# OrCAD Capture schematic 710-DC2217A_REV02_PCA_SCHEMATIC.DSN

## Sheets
1 PAGE1: size Custom; note: I²C / SMBUS TRANSLATOR
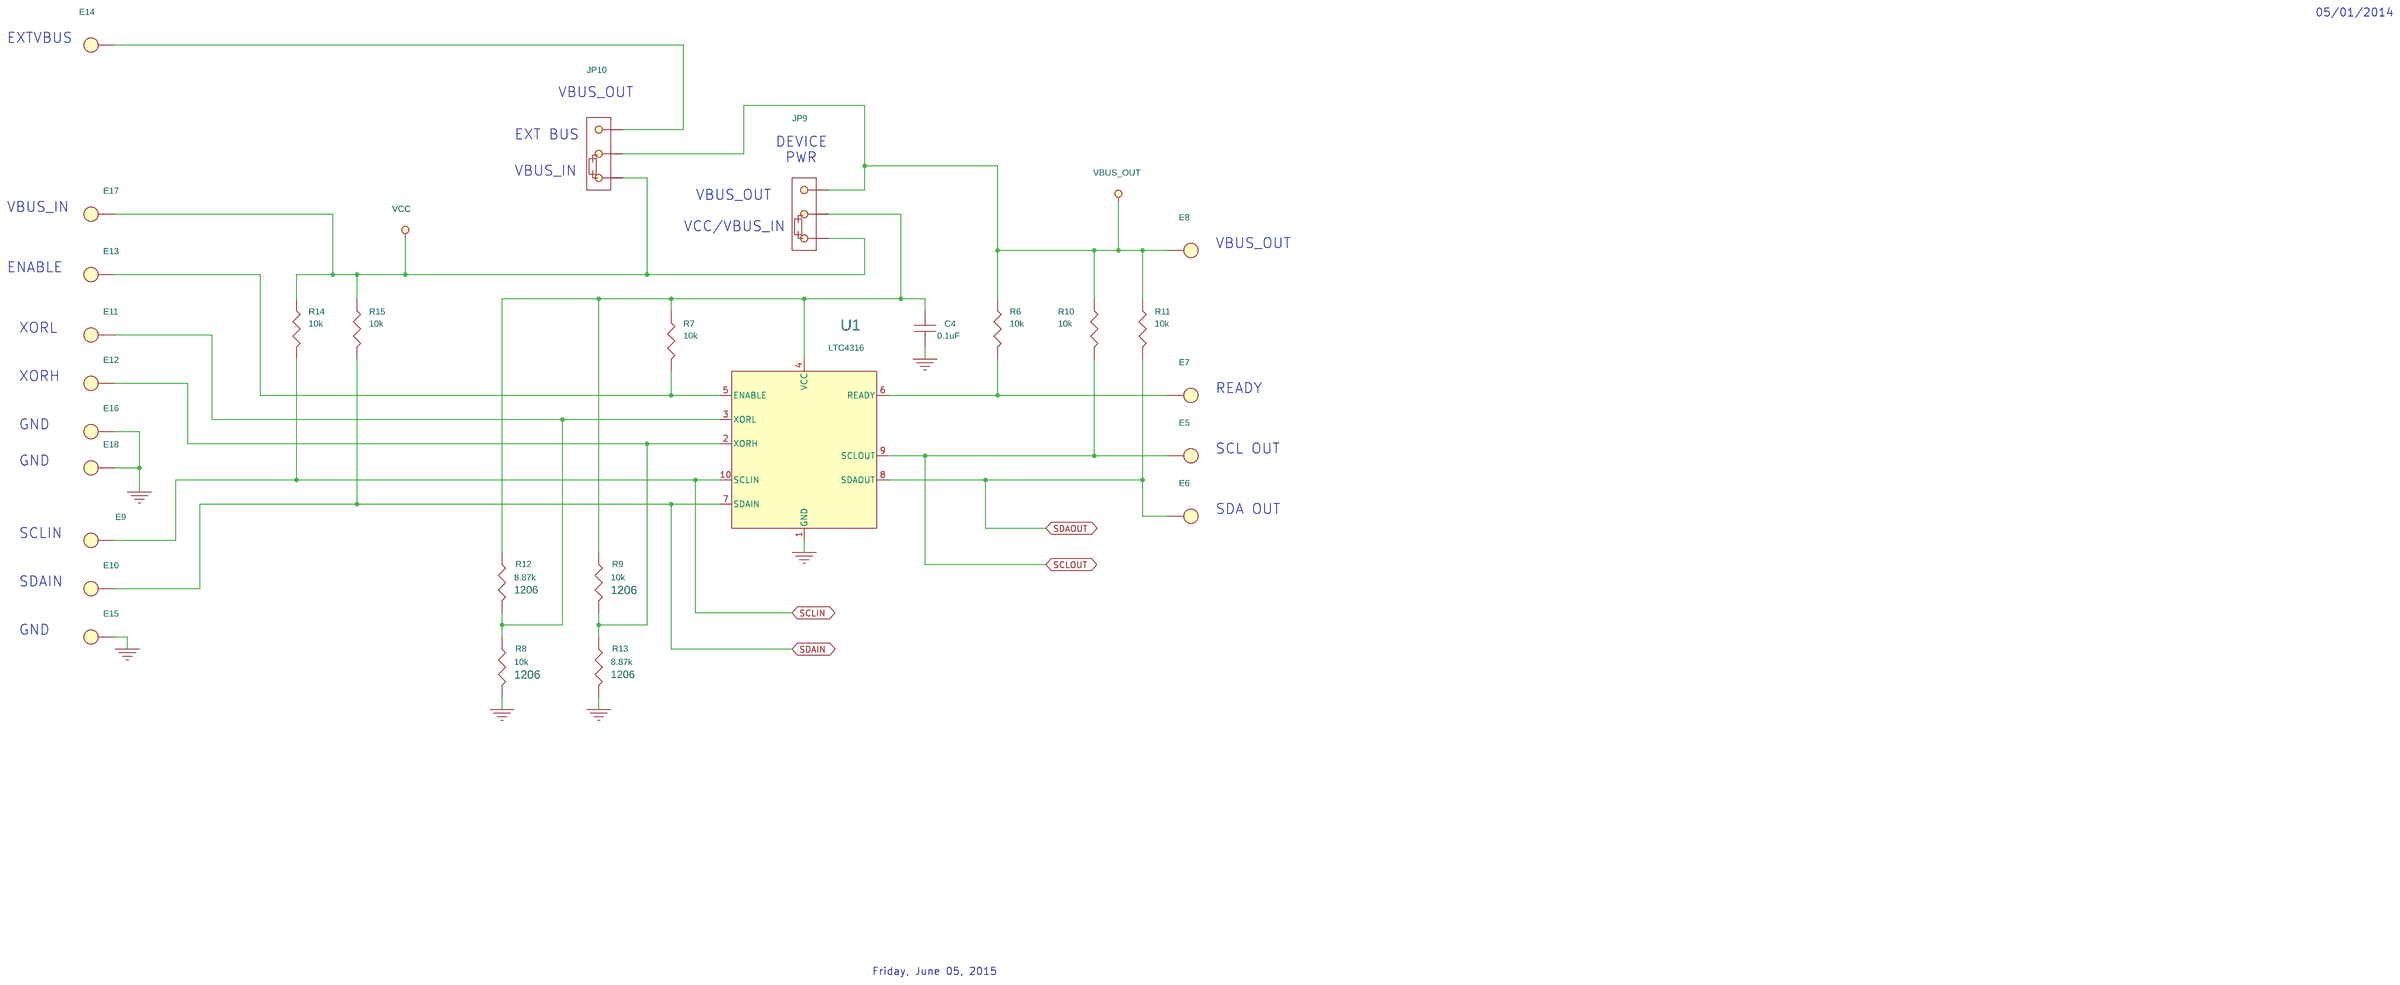
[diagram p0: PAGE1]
2 PAGE2: size Custom
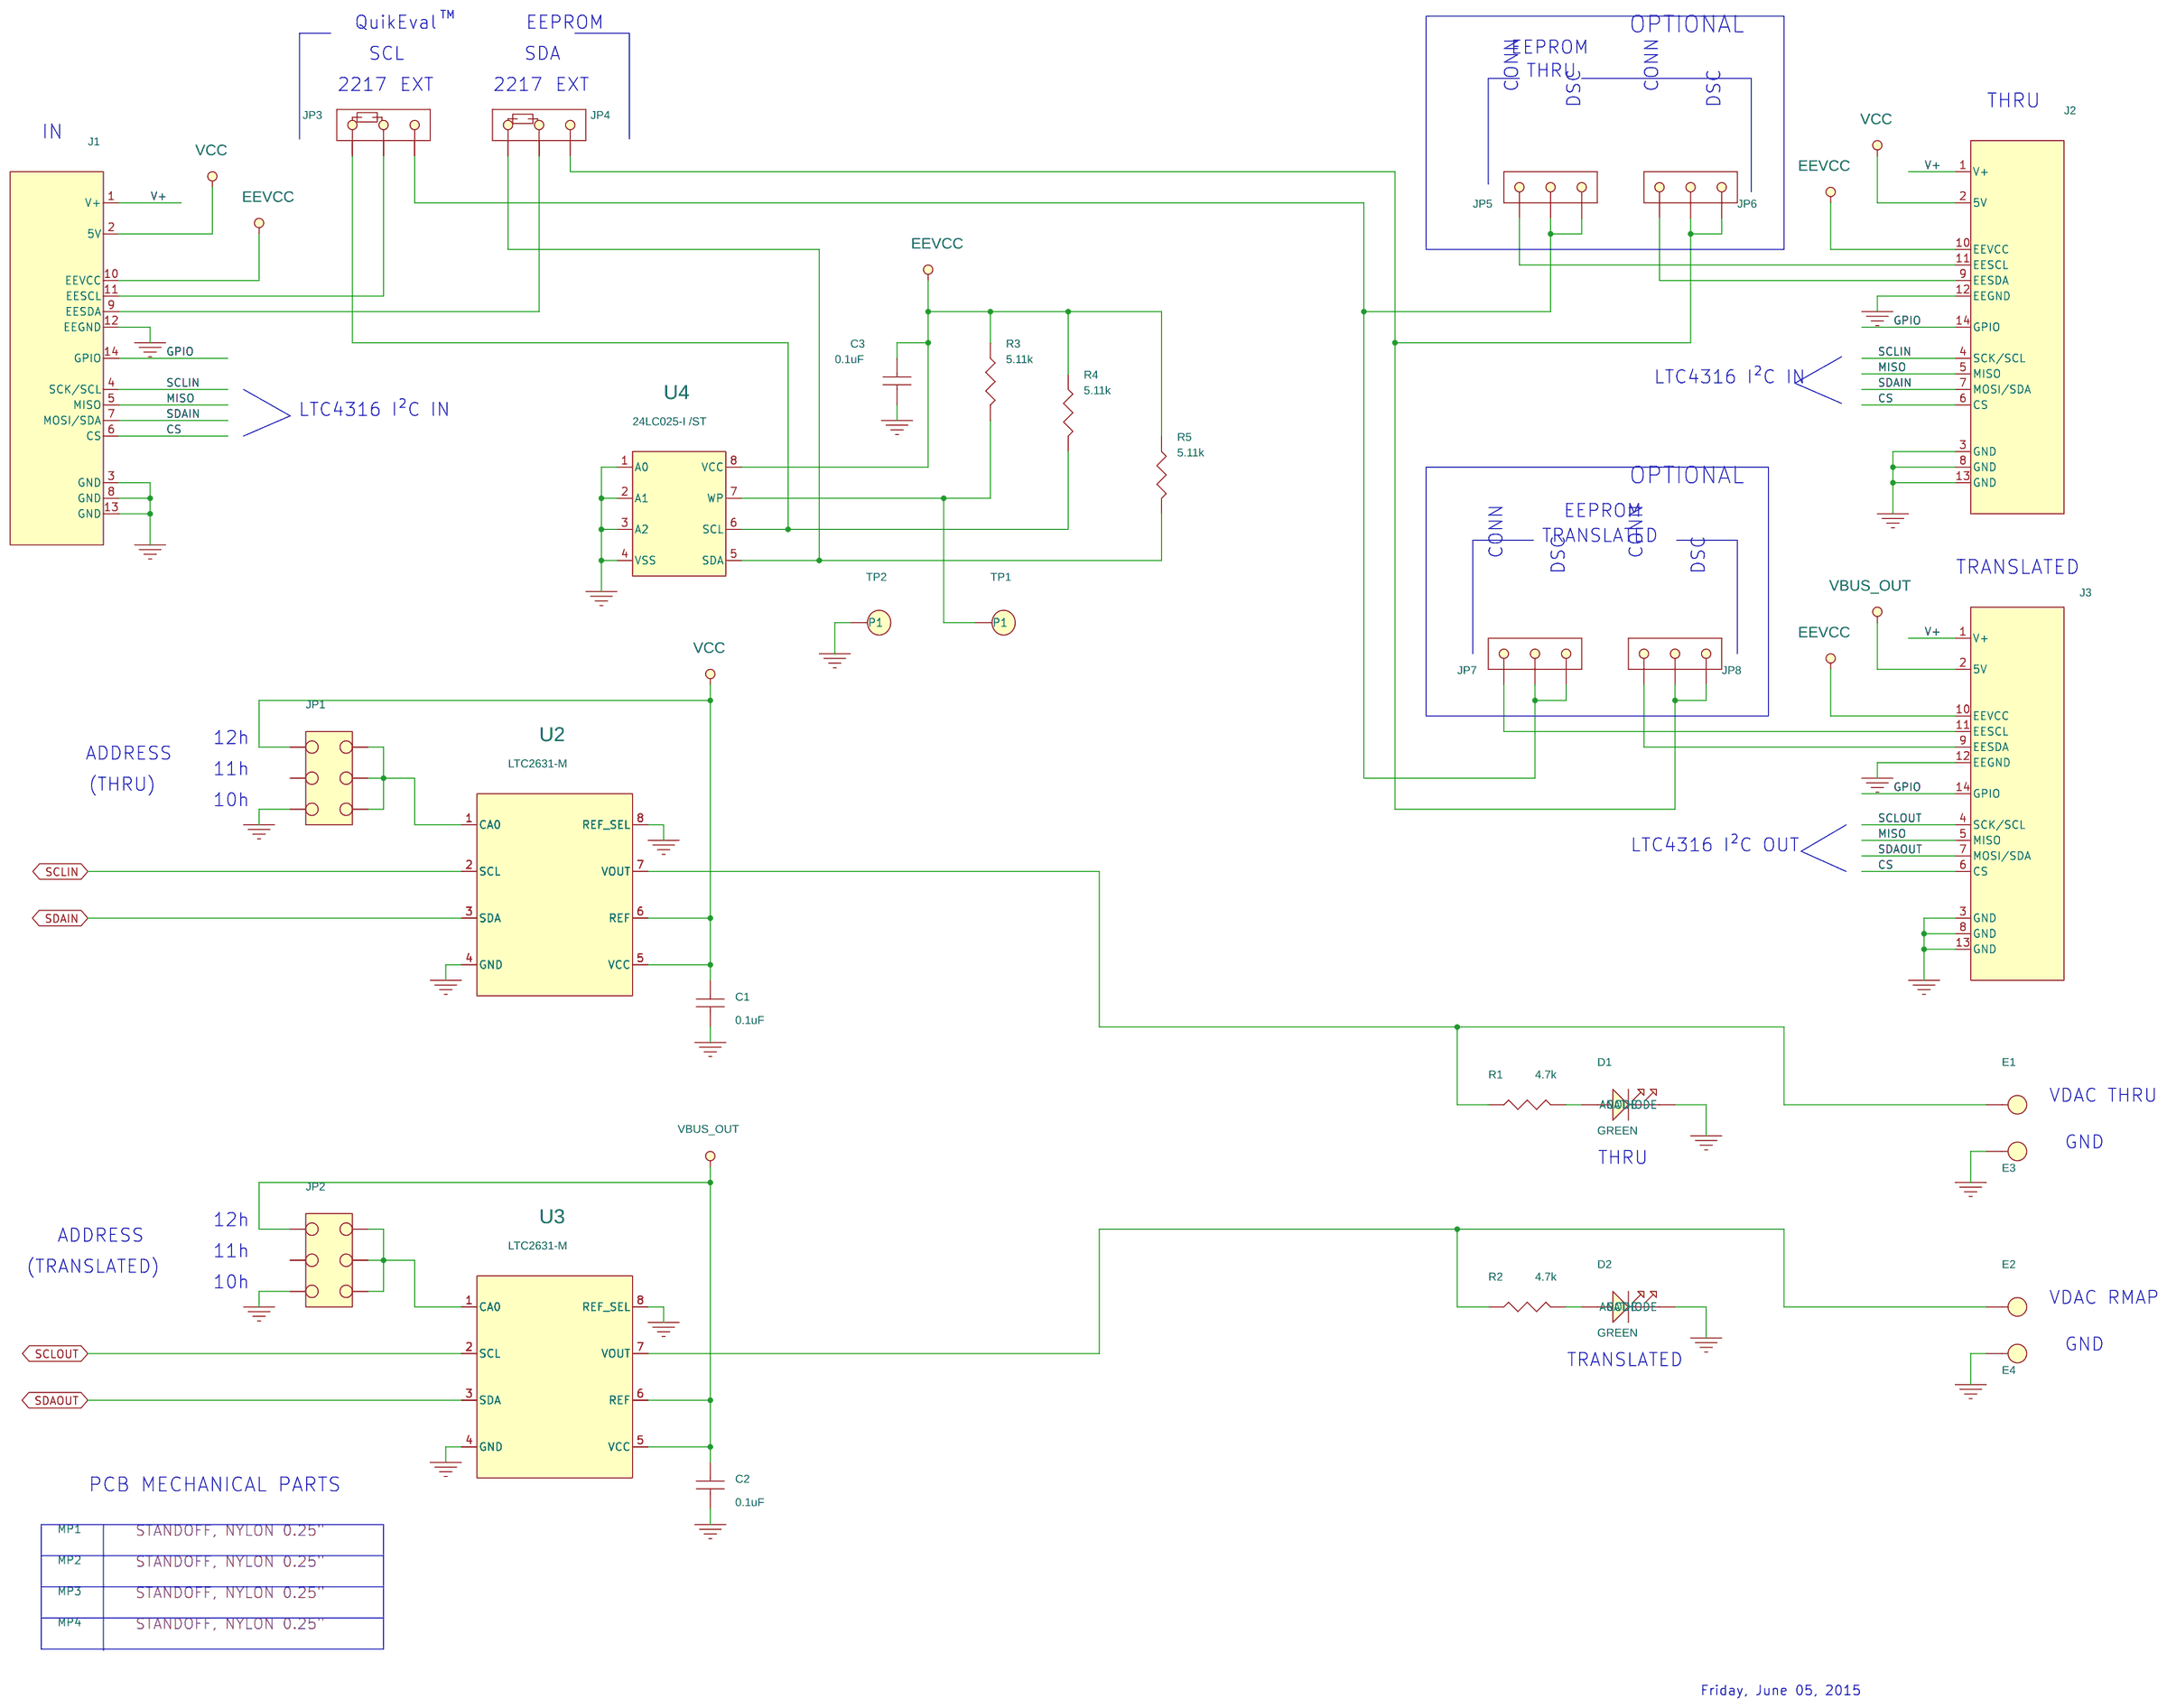
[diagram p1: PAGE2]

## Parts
sheet PAGE1
C4  0.1uF  [CC0603N]
E5  TEST POINT  [MILLMAX2308]
E6  TEST POINT  [MILLMAX2308]
E7  TEST POINT  [MILLMAX2308]
E8  TEST POINT  [MILLMAX2308]
E9  TEST POINT  [MILLMAX2308]
E10  TEST POINT  [MILLMAX2308]
E11  TEST POINT  [MILLMAX2308]
E12  TEST POINT  [MILLMAX2308]
E13  TEST POINT  [MILLMAX2308]
E14  TEST POINT  [MILLMAX2308]
E15  TEST POINT  [MILLMAX2308]
E16  TEST POINT  [MILLMAX2308]
E17  TEST POINT  [MILLMAX2308]
E18  TEST POINT  [MILLMAX2308]
JP9  HEADER  [JP3X1/079]
JP10  HEADER  [JP3X1/079]
R6  10k  [CR0603N]
R7  10k  [CR0603N]
R8  10k  [CR1206N]
R9  10k  [CR1206N]
R10  10k  [CR0603N]
R11  10k  [CR0603N]
R12  8.87k  [CR1206N]
R13  8.87k  [CR1206N]
R14  10k  [CR0603N]
R15  10k  [CR0603N]
U1  LTC4316  [LTC-MS-10-1661]
XJP5  2mm Ctrs.
XJP9  2mm Ctrs.
sheet PAGE2
C1  0.1uF  [CC0603N]
C2  0.1uF  [CC0603N]
C3  0.1uF  [CC0603N]
D1  GREEN  [WURTH_LED_0805]
D2  GREEN  [WURTH_LED_0805]
E1  TEST POINT  [MILLMAX2308]
E2  TEST POINT  [MILLMAX2308]
E3  TEST POINT  [MILLMAX2308]
E4  TEST POINT  [MILLMAX2308]
J1  2X7 RIBBON CONN.  [HD2X7-079-MOLEX]
J2  2X7 RIBBON CONN.  [HD2X7-079-MOLEX]
J3  2X7 RIBBON CONN.  [HD2X7-079-MOLEX]
JP1  HD2X3-079  [HD2X3-079]
JP2  HD2X3-079  [HD2X3-079]
JP3  HEADER  [JP3X1/079]
JP4  HEADER  [JP3X1/079]
JP5  HEADER  [JP3X1/079]
JP6  HEADER  [JP3X1/079]
JP7  HEADER  [JP3X1/079]
JP8  HEADER  [JP3X1/079]
MP1  STANDOFF  [MTG-8831]
MP2  STANDOFF  [MTG-8831]
MP3  STANDOFF  [MTG-8831]
MP4  STANDOFF  [MTG-8831]
PCB1  PCB FABRICATION
R1  4.7k  [CR0603N]
R2  4.7k  [CR0603N]
R3  5.11k  [CR0603N]
R4  5.11k  [CR0603N]
R5  5.11k  [CR0603N]
TP1  TEST PAD  [PADSTYLE2]
TP2  TEST PAD  [PADSTYLE2]
U2  LTC2631-M  [LTC-TS8]
U3  LTC2631-M  [LTC-TS8]
U4  24LC025-I /ST  [MICROCHIP-TSSOP-8]
XJP1  2mm Ctrs.
XJP2  2mm Ctrs.
XJP3  2mm Ctrs.
XJP4  2mm Ctrs.

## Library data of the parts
C1-C4 = CAP: CAP.,0.1uF,X7R,16V,10%,0603; CLASS: DISCRETE; Dielectric Type: X7R; Manufacturer: AVX; Manufacturer PN: 0603YC104KAT2A; PART_NUMBER: 150-0164; Package Size: 0603; Rated Voltage: 16V; Tolerance: 10%
E1-E18 = TEST_POINT_.156_MILL-MAX_2308: TEST POINT,TURRET,0.064" MTG. HOLE; CLASS: IO; Manufacturer PN: 2308-2-00-80-00-00-07-0; PART_NUMBER: 260-0004
JP3-JP10 = 3_PIN_HEADER_.079_SINGLE_ROW_C: CONN.,HEADER,MALE,1X3,2mm,THT; CLASS: IO; Manufacturer PN: TMM-103-02-L-S; PART_NUMBER: 250-0422
R6 R7 R10 R11 R14 R15 = RES: RES.,10k OHMS,5%,1/10W,0603; CLASS: DISCRETE; FPLIST: CR0603N,CR0603L,CR0603M; Manufacturer: YAGEO; Manufacturer PN: RC0603JR-0710KL; PART_NUMBER: 100-0005; Package Size: 0603; Rated Power: 1/10W; Temperature Coefficient: 100ppm/C; Tolerance: 5%
R8 R9 = RES: RES.,10k OHMS,5%,1/4W,1206; CLASS: DISCRETE; Manufacturer: PANASONIC; Manufacturer PN: ERJ8GEYJ103V; PART_NUMBER: 100-0317; Package Size: 1206; Rated Power: 1/4W; Temperature Coefficient: 200ppm/C; Tolerance: 5%
R12 R13 = RES: RES.,8.87k OHMS,1%,1/4W,1206; CLASS: DISCRETE; Manufacturer: Yageo; Manufacturer PN: RC1206FR-078K87L; PART_NUMBER: 100-2100; Package Size: 1206; Rated Power: 1/4W; Tolerance: 1%
U1 = LTC4316-MS: IC,I2C/SMBUS TRANSLATOR,MS10; CLASS: IC; Manufacturer: LINEAR TECHNOLOGY; Manufacturer PN: LTC4316IMS#TRPBF; PART_NUMBER: 550-0025; Package Size: TSOT-23
XJP1-XJP5 XJP9 = SHUNT_2MM_C: CONN.,SHUNT,FEMALE,2 POS,2mm; CLASS: IO; Manufacturer PN: 2SN-BK-G; PART_NUMBER: 250-0419
D1 D2 = LED_GREEN: LED,GREEN, WATERCLEAR, 0805; CLASS: DISCRETE; Manufacturer: WURTH; Manufacturer PN: 150080GS75000; PART_NUMBER: 270-0063; Package Size: 0805
J1-J3 = CONN_2X7_.079_MOLEX_RIBBON_B: CONN.,HEADER,SHROUDED,2X7,2mm,THT; CLASS: IO; Manufacturer PN: 87831-1420; PART_NUMBER: 250-0403
JP1 JP2 = HEADER_2X3_.079: CONN.,HEADER,2X3,2mm,THT; CLASS: IO; Manufacturer PN: TMM-103-02-L-D; PART_NUMBER: 250-0423
MP1-MP4 = BLANK_MECHANICAL_PART: STANDOFF, NYLON 0.25"; CLASS: MECHANICAL PART; Manufacturer: KEYSTONE; Manufacturer PN: 8831; PART_NUMBER: 763-0006
PCB1 = BLANK_PCB_PART: PCB FAB, DC2217A; BOM Notes: REV02; CLASS: PCB; Manufacturer: BAY AREA CIRCUITS; Manufacturer PN: 600-DC2217A; PART_NUMBER: 600-DC2217A
R1 R2 = RES: RES.,4.7k OHMS,5%,1/10W,0603; CLASS: DISCRETE; FPLIST: CR0603N,CR0603L,CR0603M; Manufacturer: NIC; Manufacturer PN: NRC06J472TRF; PART_NUMBER: 100-2765; Package Size: 0603; Rated Power: 1/10W; Temperature Coefficient: 200ppm/C; Tolerance: 5%
R3-R5 = RES: RES.,5.11k OHMS,1%,1/10W,0603; CLASS: DISCRETE; Manufacturer: VISHAY; Manufacturer PN: CRCW06035K11FKEA; PART_NUMBER: 100-2603; Package Size: 0603; Rated Power: 1/10W; Temperature Coefficient: 100ppm/C; Tolerance: 1%
TP1 TP2 = PAD_STYLE_D: TESTPOINT, PCB COPPER FEATURE; CLASS: IO; FPLIST: PADSTYLE1,PADSTYLE2,PADSTYLE3,PADSTYLE4,PADSTYLE5,PADSTYLE6,PADSTYLE7,PADSTYLE8; Manufacturer: N/A; Manufacturer PN: N/A; PART_NUMBER: PCBPADS-1
U2 U3 = LTC2631-M-TS8: IC,10-BIT DAC,TSOT-23; CLASS: IC; Manufacturer: LINEAR TECHNOLOGY; Manufacturer PN: LTC2631CTS8-HM10#TRMPBF; PART_NUMBER: 550-0026; Package Size: TSOT-23
U4 = 24LC025-I__ST_TSSOP-8: IC, MEMORY,I2C Serial EEPROM,2K-bit,TSSOP-8; CLASS: IC; Manufacturer: Microchip; Manufacturer PN: 24LC025-I/ST; PART_NUMBER: 380-0087; Package Size: TSSOP-8

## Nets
GND: C1.2 C2.2 C3.2 C4.2 D1.1(CATHODE) D2.1(CATHODE) E3.1(A) E4.1(A) E15.1(A) E16.1(A) E18.1(A) J1.3(GND) J1.8(GND) J1.12(EEGND) J1.13(GND) J2.3(GND) J2.8(GND) J2.12(EEGND) J2.13(GND) J3.3(GND) J3.8(GND) J3.12(EEGND) J3.13(GND) JP1.5 JP2.5 R8.2 R13.2 TP2.1(P1) U1.1(GND) U2.4(GND) U2.8(REF_SEL) U3.4(GND) U3.8(REF_SEL) U4.1(A0) U4.2(A1) U4.3(A2) U4.4(VSS)
VBUS_OUT: C2.1 E8.1(A) J3.2(5V) JP2.1 JP9.1 JP10.2 R6.1 R10.1 R11.1 U3.5(VCC) U3.6(REF)
VCC: C1.1 E17.1(A) J1.2(5V) J2.2(5V) JP1.1 JP9.3 JP10.3 R14.1 R15.1 U2.5(VCC) U2.6(REF)
CS: J1.6(CS) J2.6(CS) J3.6(CS)
EEVCC: C3.1 J1.10(EEVCC) J2.10(EEVCC) J3.10(EEVCC) R3.1 R4.1 R5.1 U4.8(VCC)
GPIO: J1.14(GPIO) J2.14(GPIO) J3.14(GPIO)
MISO: J1.5(MISO) J2.5(MISO) J3.5(MISO)
SCLIN: E9.1(A) J1.4(SCK/SCL) J2.4(SCK/SCL) R14.2 U1.10(SCLIN) U2.2(SCL)
SCLOUT: E5.1(A) J3.4(SCK/SCL) R10.2 U1.9(SCLOUT) U3.2(SCL)
SDAIN: E10.1(A) J1.7(MOSI/SDA) J2.7(MOSI/SDA) R15.2 U1.7(SDAIN) U2.3(SDA)
SDAOUT: E6.1(A) J3.7(MOSI/SDA) R11.2 U1.8(SDAOUT) U3.3(SDA)
V+: J1.1(V+) J2.1(V+) J3.1(V+)
N17497871: C4.1 JP9.2 R7.1 R9.1 R12.1 U1.4(VCC)
N17500039: E7.1(A) R6.2 U1.6(READY)
N17500225: E13.1(A) R7.2 U1.5(ENABLE)
N17515744: E12.1(A) R9.2 R13.1 U1.2(XORH)
N17515846: E11.1(A) R8.1 R12.2 U1.3(XORL)
N17580009: JP3.1 JP5.1 JP5.2 JP7.1 JP7.2
N17580023: R3.2 TP1.1(P1) U4.7(WP)
N17580025: JP4.1 JP6.1 JP6.2 JP8.1 JP8.2
N17580050: JP3.3 R4.2 U4.6(SCL)
N17580062: JP4.3 R5.2 U4.5(SDA)
N17580088: J1.11(EESCL) JP3.2
N17580104: JP1.2 JP1.4 JP1.6 U2.1(CA0)
N17580291: JP2.2 JP2.4 JP2.6 U3.1(CA0)
N17580540: J1.9(EESDA) JP4.2
N17601870: E14.1(A) JP10.1
N17795217: J2.11(EESCL) JP5.3
N17795692: J2.9(EESDA) JP6.3
N17812762: J3.11(EESCL) JP7.3
N17813181: J3.9(EESDA) JP8.3
N17847572: D1.2(ANODE) R1.2
N17848734: D2.2(ANODE) R2.2
N17852450: E1.1(A) R1.1 U2.7(VOUT)
N17856022: E2.1(A) R2.1 U3.7(VOUT)

Not connected (* = marked no-connect by the designer): JP1 3; JP2 3

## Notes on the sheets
sheet 1
- 05/01/2014
- EXTVBUS
- VBUS_OUT
- EXT BUS
- DEVICE
- PWR
- VBUS_IN
- VBUS_OUT
- VBUS_IN
- VCC/VBUS_IN
- VBUS_OUT
- ENABLE
- XORL
- XORH
- READY
- GND
- GND
- SCL OUT
- SDA OUT
- SCLIN
- SDAIN
- GND
- Friday, June 05, 2015
sheet 2
- QuikEval         EEPROM
- TM
- OPTIONAL
- EEPROM
- SCL
- SDA
- 2217
- EXT
- 2217
- EXT
- THRU
- CONN
- CONN
- THRU
- DSC
- DSC
- IN
- LTC4316 I²C IN
- LTC4316 I²C IN
- OPTIONAL
- EEPROM
- TRANSLATED
- CONN
- DSC
- CONN
- DSC
- TRANSLATED
- 12h
- ADDRESS
- (THRU)
- 11h
- 10h
- LTC4316 I²C OUT
- VDAC THRU
- GND
- THRU
- 12h
- ADDRESS
- 11h
- (TRANSLATED)
- 10h
- VDAC RMAP
- GND
- TRANSLATED
- PCB MECHANICAL PARTS
- Friday, June 05, 2015
